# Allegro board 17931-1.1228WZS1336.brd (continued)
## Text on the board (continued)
User.30: Board Accuracy Check,Nov 06 09:43:05 2018,Passed | Dummy-Static-No Shape On Layer Check,Nov 06 09:43:05 2018,354 errors | Split Plane Check,Nov 06 09:43:05 2018,354 errors
User.32: This gerber is just for your reference to find the DP impedance traces in layer L1. | DP IMPEDANCE TABLE: L1 | * - Denotes that this Impedance | is NOT used | IMP(Ohm) | *60.0 | *63.0 | *68.0 | *70.0 | *72.0 | *75.0 | *80.0 | 80.0 | *83.0 | *85.0 | 85.0 | *88.0 | *90.0 | *100.0 | 100.0 | WIDTH(mils) | 9.0/4.0 | 9.0/5.0 | 8.0/5.5 | 7.5/5.5 | 6.5/4.5 | 6.5/5.5 | 6.0/6.0 | 5.5/5.0 | 4.5/4.0 | 4.0/4.0 | 4.5/4.5 | 5.0/6.0 | 4.0/4.5 | 4.0/5.0 | 4.0/10.0 | 3.5/7.0 | TYPE | DP | Ref. Plane | L2
User.34: This gerber is just for your reference to find the SE impedance traces in layer L1. | SE IMPEDANCE TABLE: L1 | * - Denotes that this Impedance | is NOT used | IMP(Ohm) | *20.0 | *33.0 | *37.5 | *39.0 | *40.0 | 45.0 | *48.0 | 50.0 | *55.0 | WIDTH(mils) | 21.0 | 10.0 | 8.0 | 7.5 | 7.0 | 5.5 | 5.0 | 4.5 | 3.5 | TYPE | SE | Ref. Plane | L2
User.36: This gerber is just for your reference to find the DP impedance traces in layer L3. | DP IMPEDANCE TABLE: L3 | * - Denotes that this Impedance | is NOT used | IMP(Ohm) | *60.0 | *63.0 | *68.0 | *70.0 | *72.0 | *75.0 | 80.0 | *83.0 | 85.0 | *85.0 | *88.0 | *90.0 | WIDTH(mils) | 8.0/4.0 | 7.0/4.0 | 6.0/4.0 | 6.0/5.0 | 5.5/4.0 | 5.0/4.0 | 4.0/4.0 | 4.0/4.5 | 3.5/4.0 | 4.0/5.0 | 4.0/6.5 | 3.5/4.5 | 4.0/8.0 | 3.5/5.0 | TYPE | DP | Ref. Plane | L2/L4
User.38: This gerber is just for your reference to find the SE impedance traces in layer L3. | SE IMPEDANCE TABLE: L3 | * - Denotes that this Impedance | is NOT used | IMP(Ohm) | *20.0 | *33.0 | *37.5 | *39.0 | *40.0 | 45.0 | *48.0 | 50.0 | WIDTH(mils) | 16.5 | 8.0 | 6.5 | 6.0 | 5.5 | 4.5 | 4.0 | 3.5 | TYPE | SE | Ref. Plane | L2/L4
User.40: This gerber is just for your reference to find the DP impedance traces in layer L5. | DP IMPEDANCE TABLE: L5 | * - Denotes that this Impedance | is NOT used | IMP(Ohm) | *60.0 | *63.0 | *68.0 | *70.0 | *72.0 | *75.0 | *80.0 | *83.0 | 85.0 | *85.0 | *88.0 | *90.0 | *100.0 | WIDTH(mils) | 9.0/4.0 | 8.5/4.0 | 7.5/5.0 | 7.0/4.5 | 6.0/4.0 | 6.0/4.5 | 5.0/4.5 | 4.5/4.5 | 4.0/4.0 | 4.5/5.0 | 3.5/4.0 | 4.0/5.0 | 4.0/5.5 | 3.5/4.5 | 4.0/11.0 | 3.5/7.0 | TYPE | DP | Ref. Plane | L4/L7
User.42: This gerber is just for your reference to find the SE impedance traces in layer L5. | SE IMPEDANCE TABLE: L5 | * - Denotes that this Impedance | is NOT used | IMP(Ohm) | *20.0 | *33.0 | *37.5 | *39.0 | *40.0 | 45.0 | *48.0 | 50.0 | *55.0 | WIDTH(mils) | 21.0 | 10.0 | 8.0 | 7.5 | 7.0 | 5.5 | 5.0 | 4.5 | 3.5 | TYPE | SE | Ref. Plane | L4/L7
User.44: This gerber is just for your reference to find the DP impedance traces in layer L6. | DP IMPEDANCE TABLE: L6 | * - Denotes that this Impedance | is NOT used | IMP(Ohm) | *60.0 | *63.0 | *68.0 | *70.0 | *72.0 | *75.0 | *80.0 | 80.0 | *83.0 | 85.0 | *85.0 | *88.0 | *90.0 | *100.0 | WIDTH(mils) | 8.0/4.0 | 9.0/4.0 | 8.5/4.0 | 7.0/4.0 | 6.0/4.0 | 7.5/5.0 | 6.0/5.0 | 7.0/4.5 | 5.5/4.0 | 6.0/4.5 | 5.0/4.0 | 5.0/4.5 | 4.0/4.0 | 4.0/4.5 | 4.5/4.5 | 3.5/4.0 | 4.5/5.0 | 4.0/5.0 | 4.0/8.0 | 3.5/5.0 | 4.0/5.5 | 3.5/4.5 | 4.0/11.0 | 3.5/7.0 | TYPE | DP | Ref. Plane | L5/L7 | L4/L7
User.45: Note:Refer to DRILL layer for ELLIPSE drill direction | FIGURE | SIZE | 10.0 | 12.0 | 16.0 | 22.0 | 36.0 | 113.0 | 115.0 | 142.0 | 178.0 | 229.0 | 30.0 | 38.0 | 44.0 | 46.0 | 63.0 | 65.0 | 86.0 | 103.0 | 158.0 | 40.0x20.0 | 44.0x20.0 | 60.0x24.0 | 63.0x24.0 | 63.0x36.0 | 71.0x28.0 | 95.0x28.0 | 142.0x103.0 | DRILL CHART: TOP to BOTTOM | ALL UNITS ARE IN MILS | PLATED | NON-PLATED | QTY | 4962 | 24 | 707 | 19 | 26 | 1 | 5 | 7 | 3 | 2 | 8 | 4 | This gerber is just for your reference to find the DP impedance traces in layer L8. | This gerber is just for your reference to find the SE impedance traces in layer L6. | This gerber is just for your reference to find the SE impedance traces in layer L8. | DP IMPEDANCE TABLE: L8 | SE IMPEDANCE TABLE: L6 | SE IMPEDANCE TABLE: L8 | * - Denotes that this Impedance | is NOT used | Model | Bolt 2SP DIS 4GB | PCB_NO | 17931 | VER. | Layer | DRILL | L1 | L2GND | L3 | L4VCC | TMASK | TPLACE | TSILK | TSMD | Designer | YAT | Date | 12/26/2018 | IMP(Ohm) | *20.0 | *60.0 | *33.0 | *63.0 | *37.5 | *68.0 | *39.0 | *70.0 | *40.0 | *72.0 | *75.0 | 45.0 | *48.0 | *80.0 | 50.0 | *55.0 | *83.0 | 85.0 | *45.0 | *85.0 | *88.0 | 90.0 | *100.0 | *50.0 | 100.0 | WIDTH(mils) | 21.0 | 8.0 | 7.5 | 7.0 | 5.5 | 5.0 | 4.5 | 3.5 | 16.5 | 6.5 | 6.0 | 4.0 | 9.0/4.0 | 9.0/5.0 | 8.0/5.5 | 7.5/5.5 | 6.5/4.5 | 6.5/5.5 | 5.5/5.0 | 6.0/6.0 | 4.5/4.0 | 4.5/4.5 | 4.0/4.0 | 5.0/6.0 | 4.0/4.5 | 4.0/5.0 | 4.0/10.0 | 3.5/7.0 | TYPE | SE | DP | Ref. Plane | L7 | L4/L7 | L5/L7 | BMASK | BPLACE | BSILK | BSMD | L5 | L6 | L7GND | L8
